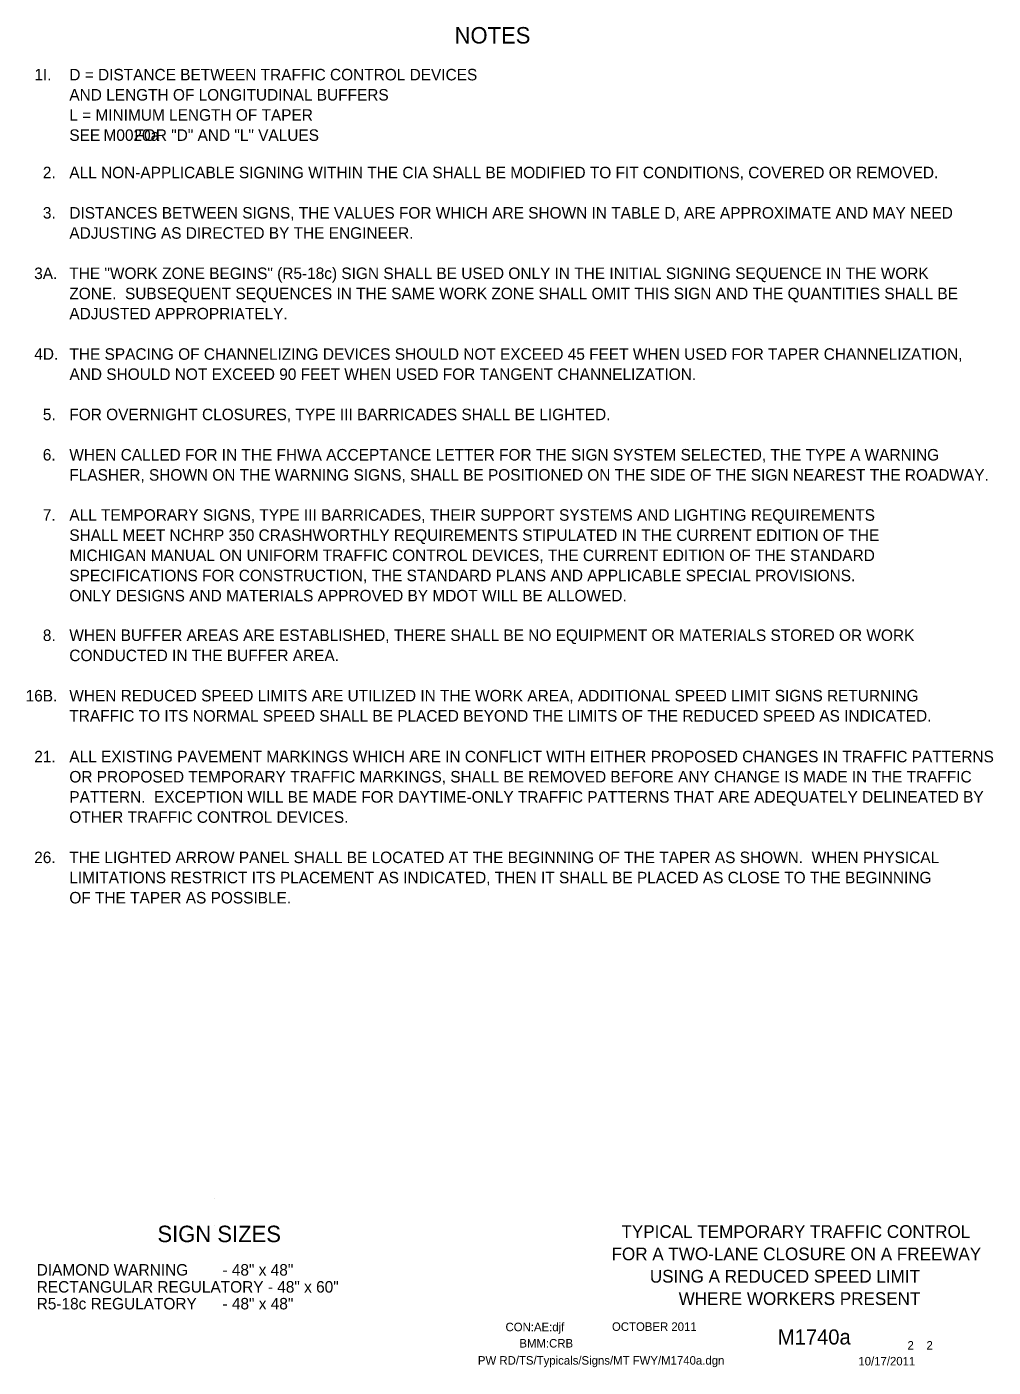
# Model space of a CAD drawing. Extents: x 16731 to 18475, y 5523 to 6928.
# Drawn here: x 17771 to 18475, y 5932 to 6909 of the extents above; entities that cross this region are included whole.
import ezdxf

# ---------------------------------------------------------------- set-up
doc = ezdxf.new("R2010")
doc.units = 0
for name, color, linetype in [('BORDER', 7, 'Continuous'), ('BORDER_SIGNAL_WO', 7, 'Continuous'), ('TYPICAL_TEXT_DIMEN_PR', 7, 'Continuous')]:
    doc.layers.add(name, color=color, linetype=linetype)

msp = doc.modelspace()

# ---------------------------------------------------------------- linework, layer by layer
at = {"layer": 'BORDER'}
for p, q in [((17907.48, 6055), (17907.48, 6055)), ((17907.48, 6035.02), (17907.48, 6035.02))]:
    msp.add_line(p, q, dxfattribs=at)

# ---------------------------------------------------------------- texts
for s, p in [('TYPICAL TEMPORARY TRAFFIC CONTROL', (18204.21, 6026.08)), ('FOR A TWO-LANE CLOSURE ON A FREEWAY', (18196.99, 6009.78)), ('USING A REDUCED SPEED LIMIT', (18224.92, 5993.48)), ('WHERE WORKERS PRESENT', (18245.92, 5977.18))]:
    msp.add_text(s, height=9.3, dxfattribs=at).set_placement(p)
at = {"layer": 'BORDER_SIGNAL_WO'}
for s, height, p in [('CON:AE:djf  ', 6.2, (18119.69, 5958.06)), ('    OCTOBER 2011', 6.2, (18188.08, 5958.34)), ('BMM:CRB', 6.2, (18129.81, 5946.17)), ('    M1740a   ', 11, (18301.86, 5948.38)), (' 2    2 ', 6.2, (18410.45, 5944.7)), ('PW RD/TS/Typicals/Signs/MT FWY/M1740a.dgn      ', 6.2, (18099.55, 5933.71)), ('10/17/2011', 6.2, (18376.93, 5933.13))]:
    msp.add_text(s, height=height, dxfattribs=at).set_placement(p)
at = {"layer": 'TYPICAL_TEXT_DIMEN_PR'}
for s, height, p in [('NOTES', 12, (18082.55, 6897)), ('1I.', 8.4, (17776.19, 6870.11)), ('D = DISTANCE BETWEEN TRAFFIC CONTROL DEVICES', 8.4, (17801.7, 6870.11)), ('AND LENGTH OF LONGITUDINAL BUFFERS', 8.4, (17801.7, 6855.41)), ('L = MINIMUM LENGTH OF TAPER', 8.4, (17801.7, 6840.71)), ('SEE        FOR "D" AND "L" VALUES', 8.4, (17801.7, 6826.01)), ('M0020a', 8.4, (17826.62, 6826.01)), ('2.', 8.4, (17782.39, 6798.75)), ('ALL NON-APPLICABLE SIGNING WITHIN THE CIA SHALL BE MODIFIED TO FIT CONDITIONS, COVERED OR REMOVED.', 8.4, (17801.7, 6798.75)), ('3.', 8.4, (17782.39, 6769.35)), ('DISTANCES BETWEEN SIGNS, THE VALUES FOR WHICH ARE SHOWN IN TABLE D, ARE APPROXIMATE AND MAY NEED', 8.4, (17801.7, 6769.35)), ('ADJUSTING AS DIRECTED BY THE ENGINEER.', 8.4, (17801.7, 6754.65)), ('THE "WORK ZONE BEGINS" (R5-18c) SIGN SHALL BE USED ONLY IN THE INITIAL SIGNING SEQUENCE IN THE WORK', 8.4, (17801.7, 6725.25)), ('3A.', 8.4, (17776.09, 6725.25)), ('ZONE.  SUBSEQUENT SEQUENCES IN THE SAME WORK ZONE SHALL OMIT THIS SIGN AND THE QUANTITIES SHALL BE', 8.4, (17801.7, 6710.55)), ('ADJUSTED APPROPRIATELY.', 8.4, (17801.7, 6695.85)), ('4D.', 8.4, (17776.13, 6666.45)), ('THE SPACING OF CHANNELIZING DEVICES SHOULD NOT EXCEED 45 FEET WHEN USED FOR TAPER CHANNELIZATION,', 8.4, (17801.8, 6666.38)), ('AND SHOULD NOT EXCEED 90 FEET WHEN USED FOR TANGENT CHANNELIZATION.', 8.4, (17801.8, 6651.68)), ('5.', 8.4, (17782.39, 6622.35)), ('FOR OVERNIGHT CLOSURES, TYPE III BARRICADES SHALL BE LIGHTED.', 8.4, (17801.7, 6622.35)), ('6.', 8.4, (17782.34, 6592.95)), ('WHEN CALLED FOR IN THE FHWA ACCEPTANCE LETTER FOR THE SIGN SYSTEM SELECTED, THE TYPE A WARNING ', 8.4, (17801.7, 6592.95)), ('FLASHER, SHOWN ON THE WARNING SIGNS, SHALL BE POSITIONED ON THE SIDE OF THE SIGN NEAREST THE ROADWAY.', 8.4, (17801.7, 6578.25)), ('7.', 8.4, (17782.34, 6549.01)), ('ALL TEMPORARY SIGNS, TYPE III BARRICADES, THEIR SUPPORT SYSTEMS AND LIGHTING REQUIREMENTS', 8.4, (17801.7, 6549.03)), ('SHALL MEET NCHRP 350 CRASHWORTHLY REQUIREMENTS STIPULATED IN THE CURRENT EDITION OF THE', 8.4, (17801.7, 6534.33)), ('MICHIGAN MANUAL ON UNIFORM TRAFFIC CONTROL DEVICES, THE CURRENT EDITION OF THE STANDARD', 8.4, (17801.7, 6519.63)), ('SPECIFICATIONS FOR CONSTRUCTION, THE STANDARD PLANS AND APPLICABLE SPECIAL PROVISIONS.', 8.4, (17801.7, 6504.93)), ('ONLY DESIGNS AND MATERIALS APPROVED BY MDOT WILL BE ALLOWED.', 8.4, (17801.7, 6490.23)), ('8.', 8.4, (17782.39, 6461.34)), ('WHEN BUFFER AREAS ARE ESTABLISHED, THERE SHALL BE NO EQUIPMENT OR MATERIALS STORED OR WORK     ', 8.4, (17801.7, 6461.34)), ('CONDUCTED IN THE BUFFER AREA.', 8.4, (17801.7, 6446.64)), ('16B.', 8.4, (17769.84, 6417.24)), ('WHEN REDUCED SPEED LIMITS ARE UTILIZED IN THE WORK AREA, ADDITIONAL SPEED LIMIT SIGNS RETURNING', 8.4, (17801.7, 6417.3)), ('TRAFFIC TO ITS NORMAL SPEED SHALL BE PLACED BEYOND THE LIMITS OF THE REDUCED SPEED AS INDICATED.', 8.4, (17801.7, 6402.6)), ('21.', 8.4, (17776.14, 6372.87)), ('ALL EXISTING PAVEMENT MARKINGS WHICH ARE IN CONFLICT WITH EITHER PROPOSED CHANGES IN TRAFFIC PATTERNS', 8.4, (17801.7, 6372.87)), ('OR PROPOSED TEMPORARY TRAFFIC MARKINGS, SHALL BE REMOVED BEFORE ANY CHANGE IS MADE IN THE TRAFFIC', 8.4, (17801.7, 6358.17)), ('PATTERN.  EXCEPTION WILL BE MADE FOR DAYTIME-ONLY TRAFFIC PATTERNS THAT ARE ADEQUATELY DELINEATED BY', 8.4, (17801.7, 6343.47)), ('OTHER TRAFFIC CONTROL DEVICES.', 8.4, (17801.7, 6328.77)), ('26.', 8.4, (17776.09, 6299.37)), ('THE LIGHTED ARROW PANEL SHALL BE LOCATED AT THE BEGINNING OF THE TAPER AS SHOWN.  WHEN PHYSICAL', 8.4, (17801.7, 6299.37)), ('LIMITATIONS RESTRICT ITS PLACEMENT AS INDICATED, THEN IT SHALL BE PLACED AS CLOSE TO THE BEGINNING', 8.4, (17801.7, 6284.67)), ('OF THE TAPER AS POSSIBLE.', 8.4, (17801.7, 6269.97)), ('SIGN SIZES', 12, (17865.92, 6023.02)), ('DIAMOND WARNING        - 48" x 48"', 8.4, (17777.88, 5998.62)), ('RECTANGULAR REGULATORY - 48" x 60"', 8.4, (17777.88, 5986.22)), ('R5-18c REGULATORY      - 48" x 48"', 8.4, (17777.88, 5973.96))]:
    msp.add_text(s, height=height, dxfattribs=at).set_placement(p)

doc.saveas('drawing.dxf')
